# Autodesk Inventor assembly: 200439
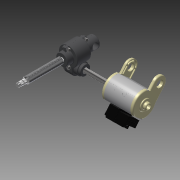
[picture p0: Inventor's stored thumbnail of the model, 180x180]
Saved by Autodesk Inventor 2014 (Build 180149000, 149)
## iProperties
Created: 2008-01
Part Number: 200439
Document SubType Name: Assembly
Designer: jjohnson
Author: jjohnson
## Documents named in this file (4)
- C:\Users\iTools\Desktop\tutorial files\Automotive\2000\200439.iam
- C:\Users\iTools\Desktop\tutorial files\Automotive\2000\206897.iam
- C:\Users\iTools\Desktop\tutorial files\Automotive\2000\201985.iam
- C:\Users\iTools\Desktop\tutorial files\Automotive\2000\203621.iam
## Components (3 placed, 3 different names)
1. 201985:1 [sub-assembly] — Insert:1
2. 206897:1 [sub-assembly] — Insert:1, Insert:2, Mate:1
3. 203621:1 [sub-assembly] — Insert:2, Mate:1
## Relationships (3: Insert 2, Mate 1)
- Insert:1: 201985:1 ↔ 206897:1
- Insert:2: 206897:1 ↔ 203621:1
- Mate:1: 206897:1 ↔ 203621:1
